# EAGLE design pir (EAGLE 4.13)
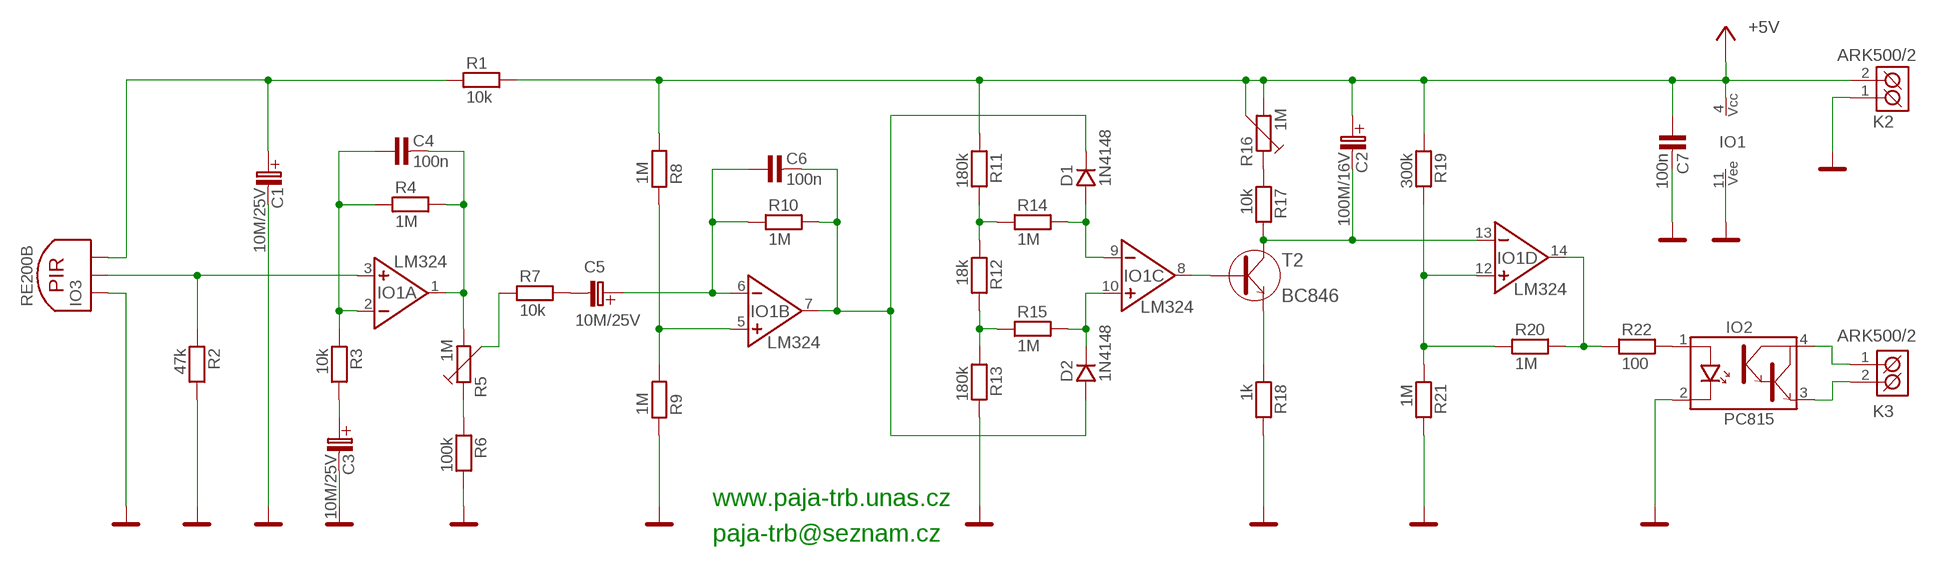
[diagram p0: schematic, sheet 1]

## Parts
C1  10M/25V  [C_EL_2]
C2  100M/16V  [C_EL_2,5]
C3  10M/25V  [C_EL_2]
C4  100n  C-KERAMIK_SMD_1206  [1206]
C5  10M/25V  [C_EL_2]
C6  100n  C-KERAMIK_SMD_1206  [1206]
C7  100n  C-KERAMIK_SMD_1206  [1206]
D1  1N4148  1N4148_SMD_SOD80  [SOD-80]
D2  1N4148  1N4148_SMD_SOD80  [SOD-80]
IO1  LM324  [DIL14]
IO2  PC815  [DIL4]
IO3  RE200B  PIR_RE200B  [RE200B]
K2  ARK500/2  [ARK500/2]
K3  ARK500/2  [ARK500/2]
R1  10k  R_SMD_1206  [1206]
R2  47k  R_SMD_1206  [1206]
R3  10k  R_SMD_1206  [1206]
R4  1M  R_SMD_1206  [1206]
R5  1M  PT-6_V-LEZ  [PT6V]
R6  100k  R_SMD_1206  [1206]
R7  10k  R_SMD_1206  [1206]
R8  1M  R_SMD_1206  [1206]
R9  1M  R_SMD_1206  [1206]
R10  1M  R_SMD_1206  [1206]
R11  180k  R_SMD_1206  [1206]
R12  18k  R_SMD_1206  [1206]
R13  180k  R_SMD_1206  [1206]
R14  1M  R_SMD_1206  [1206]
R15  1M  R_SMD_1206  [1206]
R16  1M  PT-6_V-LEZ  [PT6V]
R17  10k  R_SMD_1206  [1206]
R18  1k  R_SMD_1206  [1206]
R19  300k  R_SMD_1206  [1206]
R20  1M  R_SMD_1206  [1206]
R21  1M  R_SMD_1206  [1206]
R22  100  R_SMD_1206  [1206]
T2  BC846  [SOT-23]

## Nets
+5V: C2.C+(C_EL+) C7.1 IO1.4(POWER:VCC) K2.2(K2) R1.2 R8.2 R11.1 R16.2 R16.3 R19.1
GND: C1.C-(C_EL-) C3.C-(C_EL-) C7.2 IO1.11(POWER:VEE) IO2.2(K) IO3.GND K2.1(K1) R2.2 R6.2 R9.1 R13.2 R18.2 R21.2
N$1: C4.1 IO1.2(A:IN-) R3.1 R4.1
N$2: C4.2 IO1.1(A:VYSTUP) R4.2 R5.2
N$3: C5.C-(C_EL-) R7.2
N$4: C3.C+(C_EL+) R3.2
N$5: C5.C+(C_EL+) C6.1 IO1.6(B:IN-) R10.1
N$6: C6.2 D1.K D2.A IO1.7(B:VYSTUP) R10.2
N$7: IO1.5(B:NEIN+) R8.1 R9.2
N$8: IO1.3(A:NEIN+) IO3.SOURCE R2.1
N$9: R5.3 R7.1
N$10: C1.C+(C_EL+) IO3.DRAIN+(DRAIN) R1.1
N$11: R5.1 R6.1
N$12: R12.2 R13.1 R15.1
N$13: R11.2 R12.1 R14.1
N$14: C2.C-(C_EL-) IO1.13(D:IN-) R17.2 T2.3(C)
N$15: R16.1 R17.1
N$16: D2.K IO1.10(C:NEIN+) R15.2
N$17: D1.A IO1.9(C:IN-) R14.2
N$18: IO2.3(E) K3.2(K2)
N$19: IO1.8(C:VYSTUP) T2.2(B)
N$20: R18.1 T2.1(E)
N$22: IO1.12(D:NEIN+) R19.2 R20.1 R21.1
N$23: IO1.14(D:VYSTUP) R20.2 R22.1
N$24: IO2.1(A) R22.2
N$25: IO2.4(C) K3.1(K1)

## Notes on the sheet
- www.paja-trb.unas.cz
- paja-trb@seznam.cz

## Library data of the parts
C1 C3 C5 = #PaJa_C-el_2:10M/25V
C2 = #PaJa_C-el_2:100M/16V
C4 C6 C7 = #PaJa_21:C-KERAMIK: Kondenzator - keramicky
D1 D2 = #PaJa_21:1N4148: Univerzalni dioda - 0,15A, 75V
IO1 = #PaJa_21:LM324
IO2 = #PaJa_21:PC815: Optoclen
IO3 = #PaJa_21:PIR_RE200B
K2 K3 = #PaJa_21:ARK500/2: Svorkovnice - roztec 5mm - dvojita
R1-R4 R6-R15 R17-R22 = #PaJa_21:R: Rezistor
R5 R16 = #PaJa_21:PT-6: Trimr PT6 - 6,3mm
T2 = #PaJa_21:BC846: SMD tranzistor - NPN - ekv. BC546

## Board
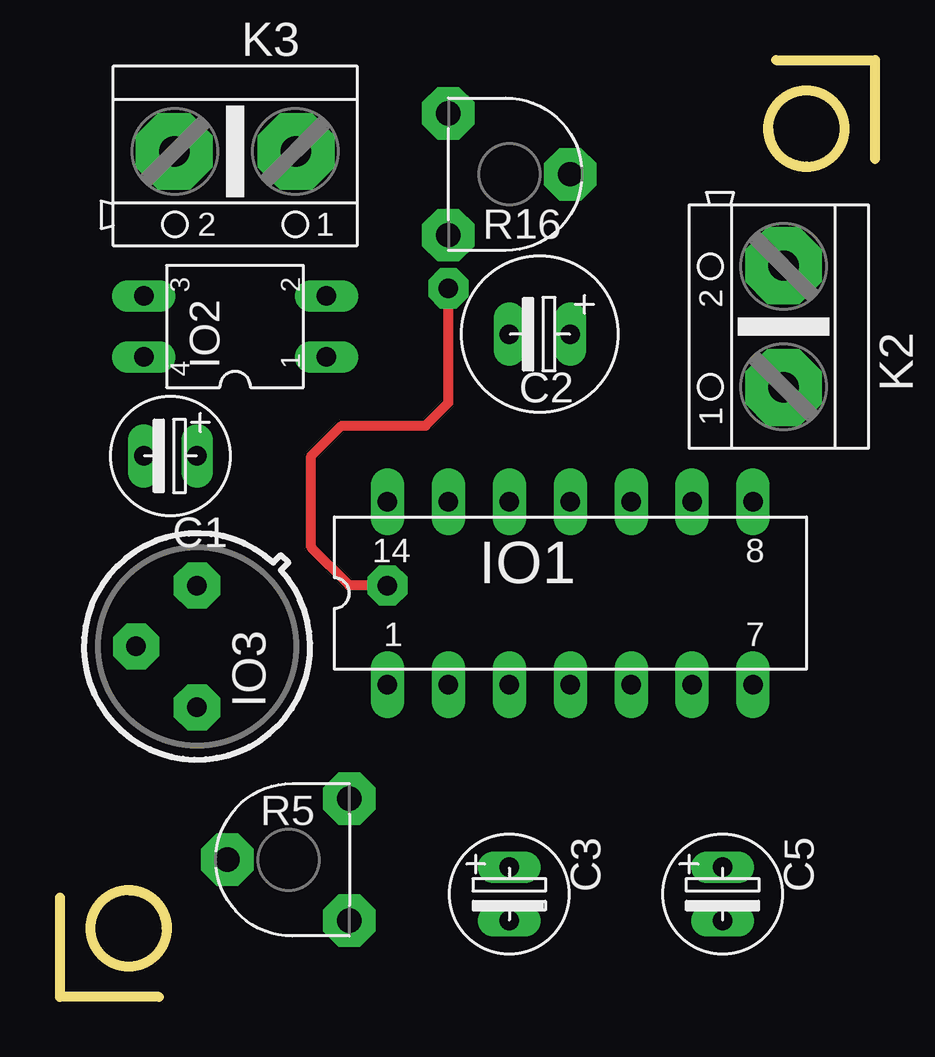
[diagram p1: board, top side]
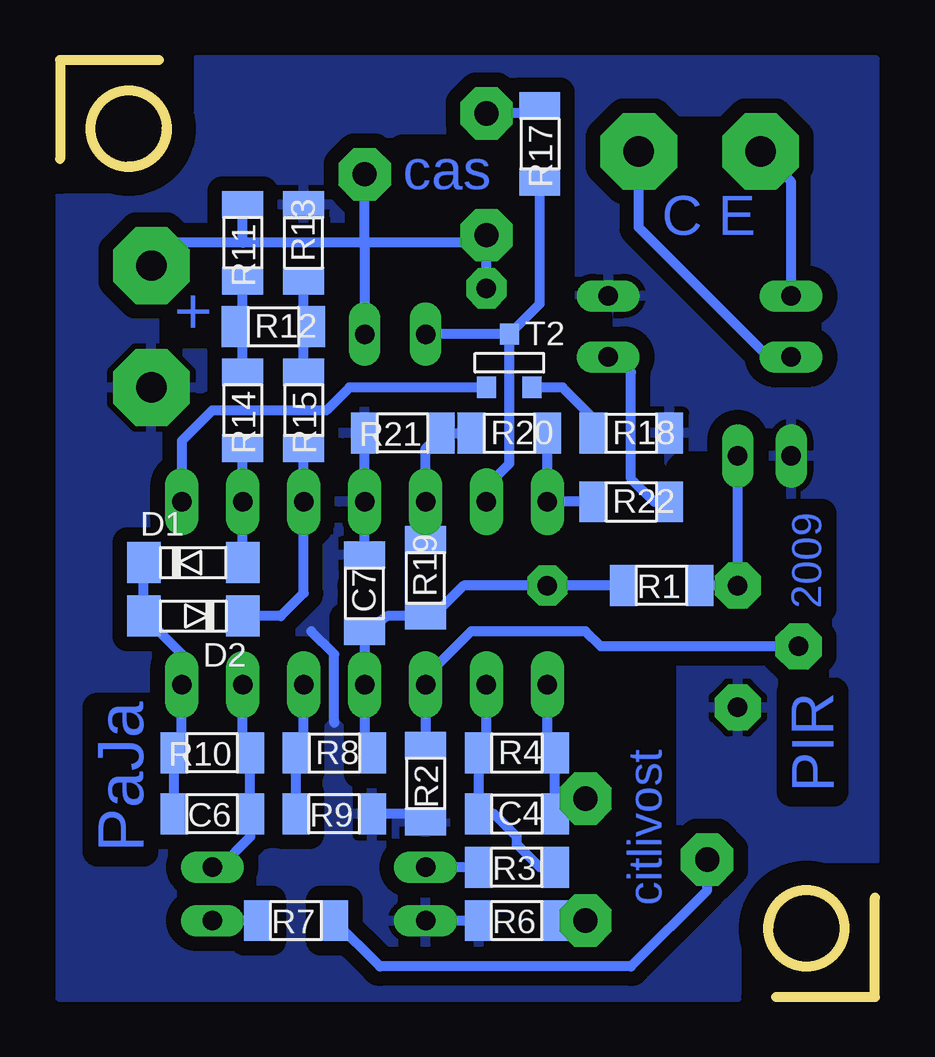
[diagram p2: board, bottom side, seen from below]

Size 33.97 x 39.05 mm. Coordinates in mm from the lower left corner, seen from the top.
Outline: 29.84,39.05 33.97,39.05 33.97,34.92
Outline: 29.53,36.2 arc90 31.11,34.61
Outline: 2.86,4.45 arc-90 4.45,2.86
Outline: 4.13,0 0,0 0,4.13
Outline: circle at 2.86,2.86 radius 1.59
Outline: circle at 31.11,36.2 radius 1.59
Copper layers (1*16): Top 0.035mm / dielectric 1.5mm / Bottom 0.035mm
Design rules "default": minimum track width 10mil, minimum drill 24mil, track to track 8mil, track to pad 8mil, pad to pad 8mil, via to via 8mil, smd to smd 8mil, copper to edge 40mil, drill to drill 8mil, minimum pad ring 10mil, minimum via ring 8mil, stop-mask expansion 4mil, vias tented up to drill 0mil, thermal gap 10mil
Holes 3.2 mm at 2.86,2.86 31.11,36.2
bRestrict: 15 lines

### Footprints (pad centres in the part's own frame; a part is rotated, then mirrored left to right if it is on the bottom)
C_EL_2 = drill 0.813 pad 1.27 long: C+ 0,0; C- 2.223,0
C_EL_2,5 = drill 0.813 pad 1.27 long: C+ -1.27,0; C- 1.27,0
1206 = smd 1.143 x 1.702: 1 -1.587,0; 2 1.587,0
SOD-80 = smd 1.397 x 1.702: A 1.905,0; K -2.223,0
DIL14 = drill 0.813 pad 1.4 long: 1 -7.62,-3.81; 2 -5.08,-3.81; 3 -2.54,-3.81; 4 0,-3.81; 5 2.54,-3.81; 6 5.08,-3.81; 7 7.62,-3.81; 8 7.62,3.81; 9 5.08,3.81; 10 2.54,3.81; 11 0,3.81; 12 -2.54,3.81; 13 -5.08,3.81; 14 -7.62,3.81
DIL4 = drill 0.813 pad 1.27 long: 1 -1.27,-3.81; 2 1.27,-3.81; 3 1.27,3.81; 4 -1.27,3.81
RE200B = drill 0.813 pad 1.93 octagon: DRAIN+ 2.54,0; GND -2.54,0; SOURCE 0,2.54
ARK500/2 = drill 1.27 pad 3.2 octagon: 1 -2.54,0; 2 2.54,0
PT6V = drill 1.016 pad 2.184 octagon: 1 -2.54,-2.54; 2 2.54,-2.54; 3 0,2.54
SOT-23 = smd 0.787 x 0.889: 1 0.953,-0.953; 2 -0.953,-0.953; 3 0,1.27

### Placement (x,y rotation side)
C1  5.71,22.54 180 top
C2  20,27.62 180 top
C3  18.73,5.4 270 top
C4  14.92,7.62 0 bottom
C5  27.62,5.4 270 top
C6  27.62,7.62 180 bottom
C7  21.27,16.83 90 bottom
D1  28.26,18.1 0 bottom
D2  28.57,15.88 180 bottom
IO1  21.27,16.83 0 top
IO2  7.3,27.94 90 top
IO3  5.71,14.61 90 top
K2  30.16,27.94 90 top
K3  7.3,35.24 180 top
R1  8.89,17.14 180 bottom
R2  18.73,8.89 270 bottom
R3  14.92,5.4 180 bottom
R4  14.92,10.16 0 bottom
R5  9.53,5.71 90 top
R6  14.92,3.17 180 bottom
R7  24.13,3.17 180 bottom
R8  22.54,10.16 0 bottom
R9  22.54,7.62 180 bottom
R10  27.62,10.16 180 bottom
R11  26.35,31.43 270 bottom
R12  25.08,27.94 0 bottom
R13  23.81,31.43 90 bottom
R14  26.35,24.45 270 bottom
R15  23.81,24.45 270 bottom
R16  18.73,34.29 270 top
R17  13.97,35.56 270 bottom
R18  10.16,23.5 0 bottom
R19  18.73,17.46 90 bottom
R20  15.24,23.5 0 bottom
R21  19.68,23.5 180 bottom
R22  10.16,20.64 0 bottom
T2  15.24,26.35 0 bottom

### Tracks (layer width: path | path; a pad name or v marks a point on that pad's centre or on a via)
+5V  (via drill 0.81 pad 1.68)
  Top 0.406: v13.65,17.14 12.06,17.14 10.48,18.73 10.48,22.54 11.75,23.81 15.24,23.81 16.19,24.77 v16.19,29.53
  Bottom 0.406: R8.2 21.27,10.16 IO1.4 C7.1 20.32,15.88 R19.1 18.41,15.88 17.14,17.14 v13.65,17.14 R1.2 | 26.35,31.43 R11.1 | 26.35,31.43 29.21,31.43 K2.2 | 21.27,31.43 26.35,31.43 | 21.27,31.43 R16.3 | 16.19,31.43 21.27,31.43 | 21.27,31.43 C2.C+ | 16.19,31.43 R16.2 | v16.19,29.53 16.19,31.43
GND
  Bottom 0.406: R21.2 IO1.11 C7.2 | R2.2 18.73,7.62 R9.1 | R6.2 C3.C- | 22.54,11.43 22.54,14.29 23.5,15.24
  pour Bottom (isolate 0.61): 28.26,39.05 28.26,36.2 arc90 31.11,33.34 33.97,33.34 33.97,0 5.71,0 5.71,2.86 arc90 2.86,5.71 0,5.71 0,39.05
N$1
  Bottom 0.406: IO1.2 16.19,10.16 R4.1 C4.1 15.88,7.62 14.92,6.67 14.92,6.35 13.97,5.4 R3.1
N$2
  Bottom 0.406: IO1.1 13.65,10.16 R4.2 13.34,8.26 | 13.34,8.26 C4.2 | R5.2 13.34,8.26
N$3
  Bottom 0.406: R7.2 C5.C-
N$4
  Bottom 0.406: R3.2 C3.C+
N$5
  Bottom 0.406: IO1.6 26.35,10.16 R10.1 C6.1 26.04,6.67 27.3,5.4 C5.C+
N$6
  Bottom 0.406: R10.2 28.89,10.48 | C6.2 R10.2 | D1.K D2.A 28.89,14.29 IO1.7 28.89,10.16 R10.2
N$7
  Bottom 0.406: IO1.5 23.81,10.16 R8.1 R9.2
N$8
  Bottom 0.406: R2.1 IO1.3 18.73,13.34 16.83,15.24 12.06,15.24 11.43,14.61 IO3.SOURCE
N$9
  Bottom 0.406: R7.1 20.64,1.27 10.16,1.27 6.99,4.45 R5.3
N$10
  Bottom 0.406: R1.1 IO3.DRAIN+ C1.C+
N$11
  Bottom 0.406: R5.1 R6.1
N$12
  Bottom 0.406: R15.1 23.81,27.62 R12.2 23.81,28.26 R13.1
N$13
  Bottom 0.406: R14.1 26.35,27.62 R12.1 26.35,27.94 R11.2
N$14
  Bottom 0.406: IO1.13 16.19,21.27 15.24,22.23 T2.3 | T2.3 C2.C- | R17.2 13.97,28.89 T2.3
N$15
  Bottom 0.406: R17.1 13.97,36.83 R16.1
N$16
  Bottom 0.406: D2.K 24.77,15.88 23.81,16.83 IO1.10 R15.2
N$17
  Bottom 0.406: D1.A IO1.9 R14.2
N$18
  Bottom 0.406: K3.2 3.49,33.97 IO2.3
N$19
  Bottom 0.406: T2.2 21.91,25.4 22.86,24.45 27.62,24.45 28.89,23.18 IO1.8
N$20
  Bottom 0.406: T2.1 13.02,25.4 11.75,24.13 R18.1
N$22
  Bottom 0.406: R20.1 R21.1 18.73,22.86 IO1.12 R19.2
N$23
  Bottom 0.406: R20.2 IO1.14 R22.1
N$24
  Bottom 0.406: R22.2 9.21,20.64 10.16,21.59 10.16,26.04 10.48,26.67 IO2.1
N$25
  Bottom 0.406: IO2.4 4.45,26.67 9.84,32.07 K3.1

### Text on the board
Bottom: cas | C E | + | 2009 | PIR | PaJa | citlivost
